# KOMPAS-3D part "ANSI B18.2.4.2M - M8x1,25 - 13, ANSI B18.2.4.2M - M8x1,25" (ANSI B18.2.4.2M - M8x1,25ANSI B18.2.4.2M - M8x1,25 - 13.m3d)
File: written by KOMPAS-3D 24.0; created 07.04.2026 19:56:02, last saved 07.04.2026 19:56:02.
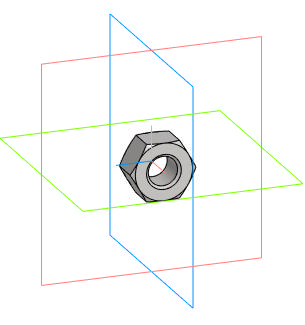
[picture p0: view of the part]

Document properties: Автор: Main; Полное имя файла: D:\DN.ru Аутсерс\Стекло смотровое DN.ru\Исходники\Стекло смотровое DN.ru SG2-34G-F тип В ГОСТ 21836-2021 Ду65 Ру16, углеродистая сталь, фланцевое\ANSI B18.2.4.2M - M8x1,25ANSI B18.2.4.2M - M8x1,25 - 13.m3d

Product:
- Body: Solid1  | qty 1
- Part/product: ANSI B18.2.4.2M - M8x1,25 - 13  | designation ANSI B18.2.4.2M - M8x1,25
    Комментарий: Типы метрических   шестигранных гаек   2
    additional columns: Сталь, мягкая

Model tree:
1. Solid1  (labels: Solid1)

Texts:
  ANSI B18.2.4.2M - M8x1,25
